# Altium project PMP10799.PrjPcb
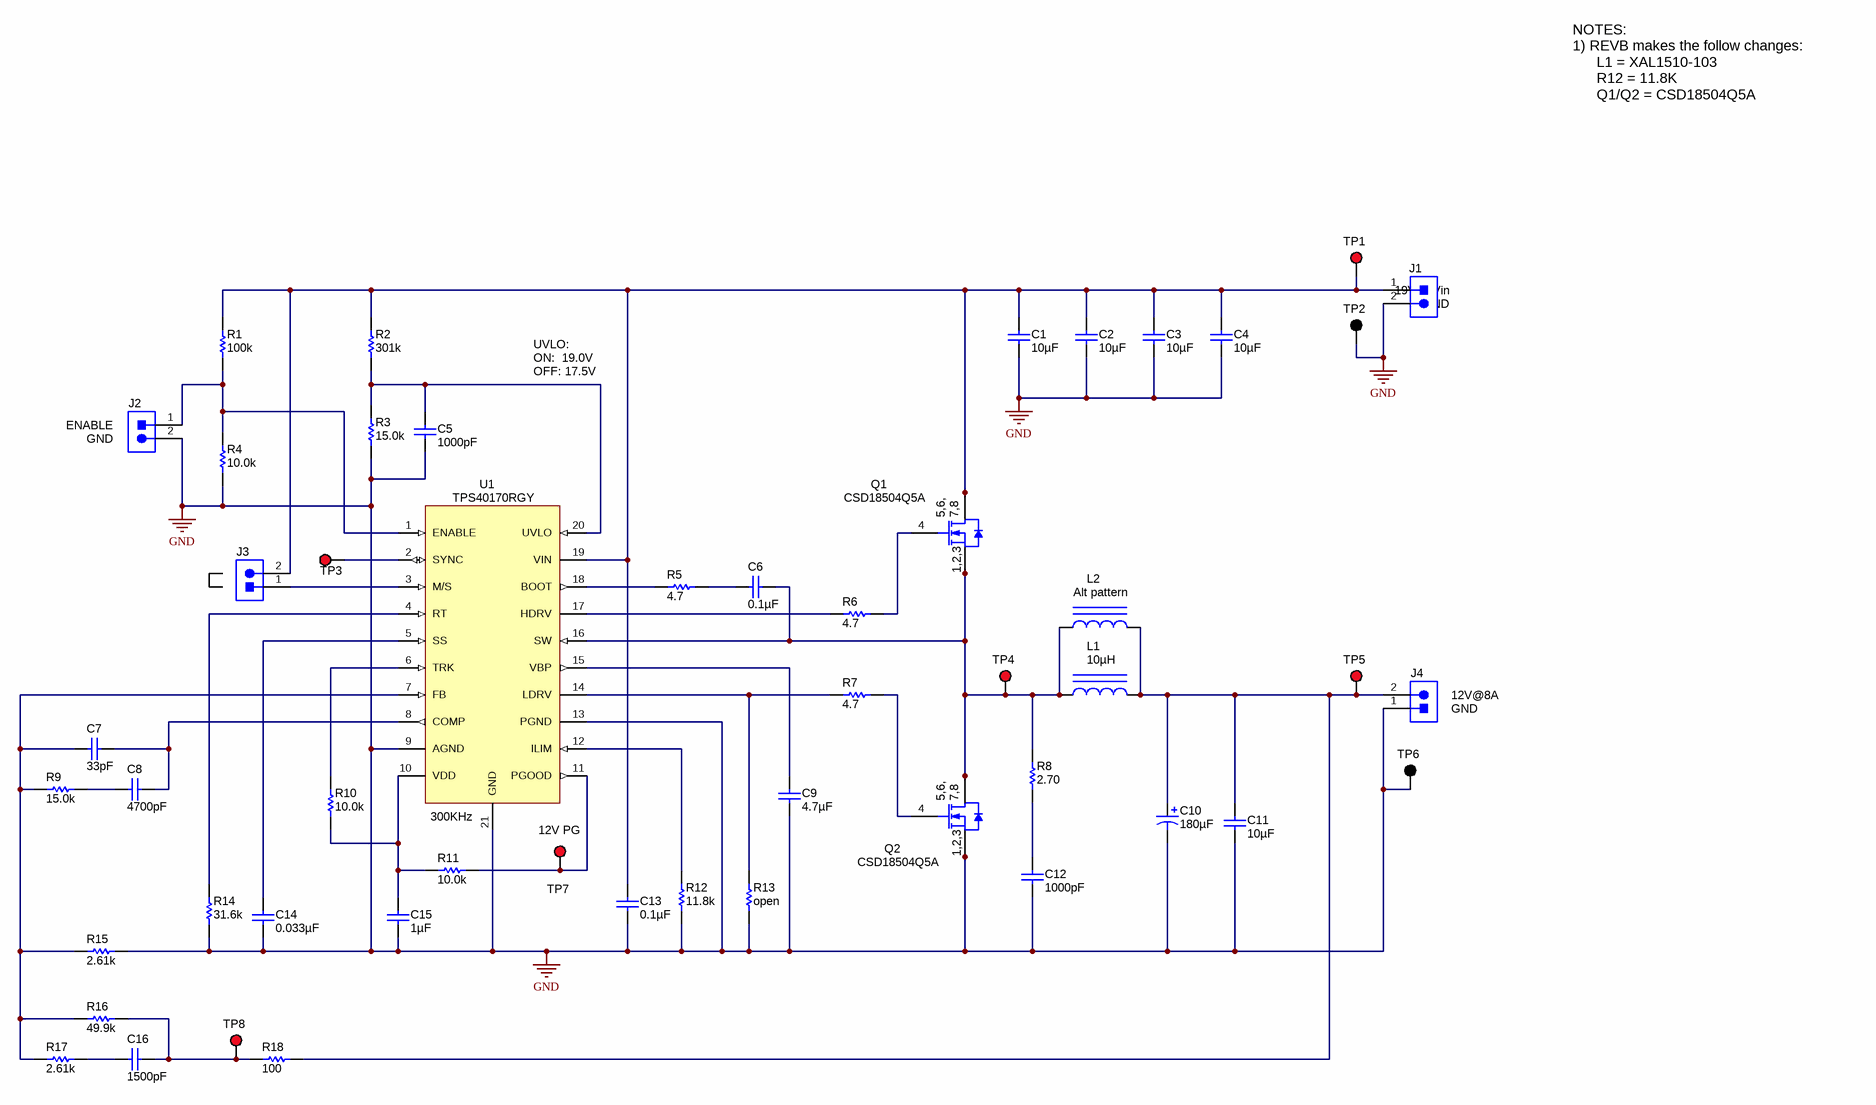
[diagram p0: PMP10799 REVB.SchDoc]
TechSupport: http://www.ti.com/support; SCH_Rev: B; PRJ_Title: TPS40170 Converter; PRJ_Number: PMP10799; PRJ_Engineer: J Betten; PRJ_Customer: Public Release; PCB_Rev: A; PCB_Layout: J Betten; EVM_Orderable: N/A; CopyrightYear: 2015
1 sheet, 51 parts. Net scope: global (net labels, ports and power ports of the same name join across sheets).
Board file: PMP10799 REVA.PcbDoc

## Sheet PMP10799 REVB.SchDoc
size 431 x 279 mm; Date: Not shown in title block; ApprovedBy: Not shown in title block; CheckedBy: Not shown in title block; Author: Not shown in title block; CompanyName: Not shown in title block; Engineer: Not shown in title block; Organization: Not shown in title block; Address1: Not shown in title block; Address2: Not shown in title block; Address3: Not shown in title block; Address4: Not shown in title block; DocumentNumber: 1; Revision: Use project parameter SCH_Rev; SheetNumber: 1; SheetTotal: 1; PageSetup: Record=PageOptions¦CenterHorizontal=True¦CenterVertical=True¦PrintScale=1.00¦XCorrection=1.00¦YCorrection=1.00¦PrintKind=0¦BorderSize=5000000¦LeftOffset=0¦BottomOffset=0¦Orientation=2¦PaperLength=1000¦PaperWidth=1000¦Scale=100¦PaperSource=15¦PrintQuality=600¦MediaType=1¦DitherType=10¦PaperKind=Letter¦PrintScaleMode=1

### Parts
C1  ValueDisplayed: 10µF  [1210]  (hidden comment: GRM32ER61H106MA12)
C2  ValueDisplayed: 10µF  [1210]  (hidden comment: GRM32ER61H106MA12)
C3  ValueDisplayed: 10µF  [1210]  (hidden comment: GRM32ER61H106MA12)
C4  ValueDisplayed: 10µF  [1210]  (hidden comment: GRM32ER61H106MA12)
C5  ValueDisplayed: 1000pF  [0603]  (hidden comment: C1608X7R1H102K)
C6  ValueDisplayed: 0.1µF  [0603]  (hidden comment: C1608X7R1H104K)
C7  ValueDisplayed: 33pF  [0603]  (hidden comment: C1608C0G1H330J)
C8  ValueDisplayed: 4700pF  [0603]  (hidden comment: C1608C0G1E472J)
C9  ValueDisplayed: 4.7µF  [0805_HV]  (hidden comment: GRM21BR71C475KA73L)
C10  ValueDisplayed: 180µF  [SM_RADIAL_6.3AMM]  (hidden comment: 16SVPF180M)
C11  ValueDisplayed: 10µF  [1206]  (hidden comment: GRM31CR71C106MAC7)
C12  ValueDisplayed: 1000pF  [0603]  (hidden comment: C1608X7R1H102K)
C13  ValueDisplayed: 0.1µF  [0603]  (hidden comment: C1608X7R1H104K)
C14  ValueDisplayed: 0.033µF  [0603]  (hidden comment: C1608X7R1H333K)
C15  ValueDisplayed: 1µF  [0603]  (hidden comment: C1608X5R1C105K)
C16  ValueDisplayed: 1500pF  [0603]  (hidden comment: C1608C0G1H152J)
J1  ED555/2DS  [TERM_BLK_ED555-2DS]  (value not drawn)
J2  PEC02SAAN  [CONN_PEC02SAAN]  (value not drawn)
J3  PEC02SAAN  [CONN_PEC02SAAN]  (value not drawn)
J4  ED555/2DS  [TERM_BLK_ED555-2DS]  (value not drawn)
L1  ValueDisplayed: 10µH  [XAL1510]  (hidden comment: XAL1510-103MEB)
L2  ValueDisplayed: Alt pattern  [MSS1210]  (hidden comment: MSS1210)
Q1  CSD18504Q5A  [TRANS_NexFET_Q5A]
Q2  CSD18504Q5A  [TRANS_NexFET_Q5A]
R1  ValueDisplayed: 100k  [0603]  (hidden comment: CRCW0603100KFKEA)
R2  ValueDisplayed: 301k  [0603]  (hidden comment: CRCW0603301KFKEA)
R3  ValueDisplayed: 15.0k  [0603]  (hidden comment: CRCW060315K0FKEA)
R4  ValueDisplayed: 10.0k  [0603]  (hidden comment: CRCW060310K0FKEA)
R5  ValueDisplayed: 4.7  [0603]  (hidden comment: CRCW06034R70JNEA)
R6  ValueDisplayed: 4.7  [0603]  (hidden comment: CRCW06034R70JNEA)
R7  ValueDisplayed: 4.7  [0603]  (hidden comment: CRCW06034R70JNEA)
R8  ValueDisplayed: 2.70  [1206]  (hidden comment: ERJ-8RQF2R7V)
R9  ValueDisplayed: 15.0k  [0603]  (hidden comment: CRCW060315K0FKEA)
R10  ValueDisplayed: 10.0k  [0603]  (hidden comment: CRCW060310K0FKEA)
R11  ValueDisplayed: 10.0k  [0603]  (hidden comment: CRCW060310K0FKEA)
R12  ValueDisplayed: 11.8k  [0603]  (hidden comment: CRCW060311K8FKEA)
R13  ValueDisplayed: open  [0603]
R14  ValueDisplayed: 31.6k  [0603]  (hidden comment: CRCW060331K6FKEA)
R15  ValueDisplayed: 2.61k  [0603]  (hidden comment: CRCW06032K61FKEA)
R16  ValueDisplayed: 49.9k  [0603]  (hidden comment: CRCW060349K9FKEA)
R17  ValueDisplayed: 2.61k  [0603]  (hidden comment: CRCW06032K61FKEA)
R18  ValueDisplayed: 100  [0603]  (hidden comment: CRCW0603100RFKEA)
TP1  5000  [Keystone5000]  (value not drawn)
TP2  5001  [Keystone5001]  (value not drawn)
TP3  5000  [Keystone5000]  (value not drawn)
TP4  5000  [Keystone5000]  (value not drawn)
TP5  5000  [Keystone5000]  (value not drawn)
TP6  5001  [Keystone5001]  (value not drawn)
TP7  5000  [Keystone5000]  (value not drawn)
TP8  5000  [Keystone5000]  (value not drawn)
U1  TPS40170RGY  [RGY0020A]

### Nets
GND: C1.1 C2.1 C3.1 C4.1 C5.2 C9.2 C10.2(-) C11.2 C12.2 C13.1 C14.2 C15.2 J1.2 J2.2 J4.1 Q2.1(S) Q2.2(S) Q2.3(S) R3.1 R4.2 R12.1 R13.1 R14.1 R15.2 TP2.1 TP6.1 U1.9(AGND) U1.13(PGND) U1.21(GND)
NetC1_2: C1.2 C2.2 C3.2 C4.2 C13.2 J1.1 J3.2 Q1.5(D) Q1.6(D) Q1.7(D) Q1.8(D) Q1.9(D) R1.1 R2.2 TP1.1 U1.19(VIN)
NetC5_1: C5.1 R2.1 R3.2 U1.20(UVLO)
NetC6_1: C6.1 L1.1 L2.1 Q1.1(S) Q1.2(S) Q1.3(S) Q2.5(D) Q2.6(D) Q2.7(D) Q2.8(D) Q2.9(D) R8.2 TP4.1 U1.16(SW)
NetC6_2: C6.2 R5.1
NetC7_1: C7.1 R9.2 R15.1 R16.2 R17.2 U1.7(FB)
NetC7_2: C7.2 C8.2 U1.8(COMP)
NetC8_1: C8.1 R9.1
NetC9_1: C9.1 U1.15(VBP)
NetC10_1: C10.1(+) C11.1 J4.2 L1.2 L2.2 R18.2 TP5.1
NetC12_1: C12.1 R8.1
NetC14_1: C14.1 U1.5(SS)
NetC15_1: C15.1 R10.2 R11.2 U1.10(VDD)
NetC16_1: C16.1 R17.1
NetC16_2: C16.2 R16.1 R18.1 TP8.1
NetJ2_1: J2.1 R1.2 R4.1 U1.1(ENABLE)
NetJ3_1: J3.1 U1.3(M/S)
NetQ1_4: Q1.4(G) R6.1
NetQ2_4: Q2.4(G) R7.1
NetR5_2: R5.2 U1.18(BOOT)
NetR6_2: R6.2 U1.17(HDRV)
NetR7_2: R7.2 R13.2 U1.14(LDRV)
NetR10_1: R10.1 U1.6(TRK)
NetR11_1: R11.1 TP7.1 U1.11(PGOOD)
NetR12_2: R12.2 U1.12(ILIM)
NetR14_2: R14.2 U1.4(RT)
NetTP3_1: TP3.1 U1.2(SYNC)

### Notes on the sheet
- NOTES:
  1) REVB makes the follow changes:
  L1 = XAL1510-103
  R12 = 11.8K
  Q1/Q2 = CSD18504Q5A
- UVLO:
- (near J1) 19V-32Vin
- (near J1) GND
- OFF: 17.5V
- ON:  19.0V
- (near J2) ENABLE
- (near J2) GND
- (near J4) 12V@8A
- (near J4) GND
- (near U1) 300KHz
- 12V PG

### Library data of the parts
C1-C4 = C3225X7R1E106M: CAP, CERM, 10uF, 50V, +/-20%, X5R, 1210; Manufacturer: MuRata; Polarized: N; CompType: Capacitor; U/M: EA; Cap_F: 0.00001; Tolerance_%: 20; ESR_Ohm: 0.0027; Value1: 0.0027 ohm; VDC_V: 50; IRMS_A: 3; TaMin_C: -55; TaMax_C: 125
C5 C12 = C1608X7R1H102K: CAP, CERM, 1000 pF, 50 V, +/- 10%, X7R, 0603; Manufacturer: TDK; Polarized: N; CompType: Capacitor; Value: 1000pF; U/M: EA; Cap_F: 0.000000001; Tolerance_%: 10; ESR_ohm: 0.24; Value1: 0.24 ohm; VDC_V: 50; Value2: 50V; TaMin_C: -55; TaMax_C: 125
C6 C13 = C1608X7R1H104K: CAP, CERM, 0.1uF, 50V, +/-10%, X7R, 0603; Manufacturer: TDK; Polarized: N; CompType: Capacitor; U/M: EA; Cap_F: 0.0000001; Tolerance_%: 10; ESR_Ohm: 0.017; Value1: 0.017 ohm; VDC_V: 50; TaMin_C: -55; TaMax_C: 125
C7 = C1608C0G1H330J: CAP, CERM, 33 pF, 50 V, +/- 5%, C0G/NP0, 0603; Manufacturer: TDK; Polarized: N; CompType: Capacitor; Value: 33pF; U/M: EA; Cap_F: 0.000000000033; Tolerance_%: 5; ESR_ohm: 0.2649; Value1: 0.2649 ohm; VDC_V: 50; Value2: 50V; TaMin_C: -55; TaMax_C: 125
C8 = C1608C0G1E472J: CAP, CERM, 4700 pF, 25 V, +/- 5%, C0G/NP0, 0603; Manufacturer: TDK; Polarized: N; CompType: Capacitor; Value: 4700pF; U/M: EA; Cap_F: 0.0000000047; Tolerance_%: 5; Value1: Unknown; VDC_V: 25; Value2: 25V; TaMin_C: -55; TaMax_C: 125
C9 = GRM21BR71C475KA73L: CAP, CERM, 4.7 µF, 16 V, +/- 10%, X7R, 0805; Manufacturer: MuRata; Polarized: N; CompType: Capacitor; Value: 4.7uF; U/M: EA; Cap_F: 0.0000047; Tolerance_%: 10; ESR_ohm: 0.006; Value1: 0.006 ohm; VDC_V: 16; Value2: 16V; TaMin_C: -55; TaMax_C: 125; Cap_Case: 0805
C10 = 16SVP39M: CAP, OS-CON, 180 µF, 16 V, +/- 20%, 0.022 ohm, 6.3x5.9 SMD; Manufacturer: Sanyo; Polarized: Y; CompType: Capacitor; Value: 180uF; U/M: EA; Cap_F: 0.000039; Tolerance_%: 20; VDC_V: 16; Value2: 16V; ESR_ohm: 0.05; IRMS_A: 1.62; TaMin_C: -55; TaMax_C: 105; Cap_Case: 6.6x6.6x5.9
C11 = GRM31CR71C106KAC7L: CAP, CERM, 10 µF, 16 V, +/- 20%, X7R, 1206; Manufacturer: MuRata; Polarized: N; CompType: Capacitor; Value: 10uF; U/M: EA; Cap_F: 0.00001; Tolerance_%: 10; Value1: Unknown; VDC_V: 16; Value2: 16V; TaMin_C: -55; TaMax_C: 125
C14 = C1608X7R1H473K: CAP, CERM, 0.033 µF, 50 V, +/- 10%, X7R, 0603; Manufacturer: TDK; Polarized: N; CompType: Capacitor; Value: 0.033uF; U/M: EA; Cap_F: 0.000000047; Tolerance_%: 10; ESR_ohm: 0.0234; Value1: 0.0234 ohm; VDC_V: 50; Value2: 50V; TaMin_C: -55; TaMax_C: 125
C15 = C1608X5R1C105K: CAP, CERM, 1 µF, 16 V, +/- 10%, X5R, 0603; Manufacturer: TDK; Polarized: N; CompType: Capacitor; Value: 1uF; U/M: EA; Cap_F: 0.000001; Tolerance_%: 10; ESR_ohm: 0.0057; Value1: 0.0057 ohm; VDC_V: 16; Value2: 16V; TaMin_C: -55; TaMax_C: 85
C16 = C1608C0G1H152J: CAP, CERM, 1500 pF, 50 V, +/- 5%, C0G/NP0, 0603; Manufacturer: TDK; Polarized: N; CompType: Capacitor; Value: 1500pF; U/M: EA; Cap_F: 0.0000000015; Tolerance_%: 5; ESR_ohm: 0.039; Value1: 0.039 ohm; VDC_V: 50; Value2: 50V; TaMin_C: -55; TaMax_C: 125
J1 J4 = ED555/2DS: Terminal Block, 6A, 3.5mm Pitch, 2-Pos, TH; Manufacturer: On-Shore Technology; SymbolCreator: a0412235; CompType: Connector; U/M: EA
J2 J3 = PEC02SAAN: Header, 100mil, 2x1, Tin, TH; Manufacturer: Sullins Connector Solutions; SymbolCreator: a0412235; U/M: EA
L1 = XAL1510-103MEB: Inductor, Shielded, Composite, 10 µH, 22 A, 0.0068 ohm, SMD; Manufacturer: Coilcraft; Value: 10uH; Ind_H: 10.0E-6; Imax_A: 22; Irms: 22A @ 40C rise; Isat: 26.3A @ 30% inductance drop; DCR_ohm: 0.0068; Value2: 22A
L2 = MSS1210-103ME: Inductor, open, SMD; Ind_H: 10.0E-6; Imax_A: 10; Irms: 10A @ 40C rise; Isat: 12.5A @ 30% inductance drop; DCR_ohm: 0.014; Material: Ferrite
Q1 Q2 = CSD18504Q5A: MOSFET, N-CH, 40 V, 15 A, SON 5x6mm; Manufacturer: Texas Instruments; Alternate Manufacturer: None; U/M: EA; ChType: N; Value: 40V; VdsMax_V: 40; Value1: 0.0098 ohm; Rdson45_ohm: 0.0098; Value2: 7.7 nC; QgTyp_nC: 7.7; Vgs_V: 20; IdsMax_A: 15
R1 = CRCW0603100KFKEA: RES, 100 k, 1%, 0.1 W, 0603; Manufacturer: Vishay-Dale; CompType: Resistor; Value: 100k; Res_ohm: 100000; Tolerance_%: 1; Power_W: 0.1; Value2: 0.1W; VDC_V: 75; TempCo: 100 ppm/C; EIA_Code: E96; U/M: EA
R2 = CRCW0603301KFKEA: RES, 301 k, 1%, 0.1 W, 0603; Manufacturer: Vishay-Dale; CompType: Resistor; Value: 301k; Res_ohm: 301000; Tolerance_%: 1; Power_W: 0.1; Value2: 0.1W; VDC_V: 75; TempCo: 100 ppm/C; EIA_Code: E96; U/M: EA
R3 R9 = CRCW060315K0FKEA: RES, 15.0 k, 1%, 0.1 W, 0603; Manufacturer: Vishay-Dale; CompType: Resistor; Value: 15.0k; Res_ohm: 15000; Value_Code: 15k0; Tolerance_%: 1; Power_W: 0.1; Value2: 0.1W; VDC_V: 75; TempCo: 100 ppm/C; EIA_Code: E96; U/M: EA
R4 R10 R11 = CRCW060310K0FKEA: RES, 10.0 k, 1%, 0.1 W, 0603; Manufacturer: Vishay-Dale; CompType: Resistor; Value: 10.0k; Res_ohm: 10000; Value_Code: 10k0; Tolerance_%: 1; Power_W: 0.1; Value2: 0.1W; VDC_V: 75; TempCo: 100 ppm/C; EIA_Code: E96; U/M: EA
R5-R7 = CRCW06034R70JNEA: RES, 4.7, 5%, 0.1 W, 0603; Manufacturer: Vishay-Dale; CompType: Resistor; Value: 4.7; Value_Code: 4R70; Tolerance_%: 5; Power_W: 0.1; Value2: 0.1W; VDC_V: 75; TempCo: 200 ppm/C; EIA_Code: E24; U/M: EA
R8 = ERJ-8RQF2R7V: RES, 2.70, 1%, 0.25 W, 1206; Manufacturer: Panasonic; CompType: Resistor; Value: 2.70; Res_ohm: 2.7; Value_Code: 2R70; Tolerance_%: 1; Power_W: 0.25; Value2: 0.25W; TempCo: 200 ppm/C; U/M: EA
R12 = CRCW060311K8FKEA: RES, 11.8 k, 1%, 0.1 W, 0603; Manufacturer: Vishay-Dale; CompType: Resistor; Value: 11.8k; Res_ohm: 11800; Value_Code: 11k8; Tolerance_%: 1; Power_W: 0.1; Value2: 0.1W; VDC_V: 75; TempCo: 100 ppm/C; EIA_Code: E96; U/M: EA
R13 = CRCW06037K87FKEA: RES, open, 0603; CompType: Resistor; Tolerance_%: 1; Value1: 1%; Power_W: 0.1; Value2: 0.1W; TempCo: 100 ppm/C; EIA_Code: E96; U/M: EA
R14 = CRCW060331K6FKEA: RES, 31.6 k, 1%, 0.1 W, 0603; Manufacturer: Vishay-Dale; CompType: Resistor; Value: 31.6k; Res_ohm: 31600; Value_Code: 31k6; Tolerance_%: 1; Power_W: 0.1; Value2: 0.1W; VDC_V: 75; TempCo: 100 ppm/C; EIA_Code: E96; U/M: EA
R15 R17 = CRCW06032K61FKEA: RES, 2.61 k, 1%, 0.1 W, 0603; Manufacturer: Vishay-Dale; CompType: Resistor; Value: 2.61k; Res_ohm: 2610; Value_Code: 2k61; Tolerance_%: 1; Power_W: 0.1; Value2: 0.1W; VDC_V: 75; TempCo: 100 ppm/C; EIA_Code: E96; U/M: EA
R16 = CRCW060349K9FKEA: RES, 49.9 k, 1%, 0.1 W, 0603; Manufacturer: Vishay-Dale; CompType: Resistor; Value: 49.9k; Res_ohm: 49900; Value_Code: 49k9; Tolerance_%: 1; Power_W: 0.1; Value2: 0.1W; VDC_V: 75; TempCo: 100 ppm/C; EIA_Code: E96; U/M: EA
R18 = CRCW0603100RFKEA: RES, 100, 1%, 0.1 W, 0603; Manufacturer: Vishay-Dale; CompType: Resistor; Value: 100; Value_Code: 100R; Tolerance_%: 1; Power_W: 0.1; Value2: 0.1W; VDC_V: 75; TempCo: 100 ppm/C; EIA_Code: E96; U/M: EA
TP1 TP3-TP5 TP7 TP8 = 5000: Test Point, Miniature, Red, TH; Manufacturer: Keystone; CompType: Test Point Loop; U/M: EA
TP2 TP6 = 5001: Test Point, Miniature, Black, TH; Manufacturer: Keystone; CompType: Test Point Loop; U/M: EA
U1 = TPS40170RGY: 4.5-v to 60-v wide-input synchronous PWM buck controller, RGY0020A; Alternate Manufacturer: None; Manufacturer: Texas Instruments; SymbolCreator: a0412235/PADS; CompType: IC; U/M: EA

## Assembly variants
001: not fitted FID1 FID2 FID3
